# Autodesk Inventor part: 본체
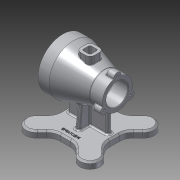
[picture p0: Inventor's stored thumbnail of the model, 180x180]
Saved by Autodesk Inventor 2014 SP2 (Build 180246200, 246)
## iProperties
Created: 2018-03
Part Number: 본체
Material: 알루미늄 6061
Document SubType Name: Modeling
Designer: 거성
Density: 2.71 g/cm^3
Appearance: 알루미늄 - 평지
Mass: 1030.73 g
Surface Area: 859.626 cm^2
Volume: 380.342 cm^3
Author: 거성
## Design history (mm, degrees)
sketch "스케치1"
  geometry: L1 (-50, 0)-(50, 0); L2 (-50, 36)-(-50, 45); L3 (-50, 45)-(-30, 45); L4 (-30, 45)-(27, 27.5); L5 (50, 27.5)-(50, 21); L6 (49, 20)-(23, 20); L7 (20, 23)-(20, 23); L8 (17, 26)-(-24, 26); L9 (-27, 29)-(-27, 32); L10 (-30, 35)-(-49, 35); L11 (27, 27.5)-(50, 27.5); L12 (-50, 36)-(-49, 35); L13 (49, 20)-(50, 21); A1 r 3 centre (-30, 32) between (-27, 32) and (-30, 35); A2 r 3 centre (-24, 29) between (-27, 29) and (-24, 26); A3 r 3 centre (17, 23) between (20, 23) and (17, 26); A4 r 3 centre (23, 23) between (20, 23) and (23, 20); 7 further points
  constraints: 26 end point, 10 point on line, 8 point on circle, 8 tangent, 7 parallel, 4 centre point, 3 equal radius, 2 perpendicular, 1 coincident, 1 horizontal, 1 midpoint
  dimensions: "d0" = 100 distance of L1.start L1.end; "d1" = 90 diameter of L3 L1; "d2" = 70 diameter of L10 L1; "d4" = 40 diameter of L6 L1; "d5" = 52 diameter of L8 L1; "d6" = 20 distance of L2.end L3.end; "d7" = 77 distance from line of L2 L4.end; "d8" = 100 distance between parallel lines of L5 L2; "d9" = 23 distance of point (-27, 35) point (-50, 35); "d10" = 47 distance of point (20, 26) point (-27, 26); "d11" = 55 diameter of L11 L1; "d12" = 49.99998 distance from line of L5 point (0, 0); "d13" = 3 radius of A1; "d14" = 1 distance of L2.start point (-50, 35); "d15" = 45 deg angle of L2 L12; "d16" = 1 distance of L6.start point (50, 20) (= d14); "d17" = 45 deg angle of L6 L13 (= d15)
revolve "회전1" sketch "스케치1" stored, may be unused: angle "d18" = 90 deg
node "작업 평면1"
sketch "스케치2"
  geometry: L1 (9.189, 45)-(-9.189, 45); L2 (-45, 9.189)-(-45, -9.189); L3 (44.289, 44.289)-(-44.289, -44.289); L4 (-45.7, 45.7)-(45.7, -45.7); L5 (115.887, 0)-(-115.887, 0); L6 (0, 0)-(84.957, -84.957); L7 (60.561, -35.105)-(52.322, -26.866); L8 (35.105, -60.561)-(26.866, -52.322); L9 (45, -9.189)-(45, 9.189); L10 (-9.189, -45)-(9.189, -45); L11 (35.105, 60.561)-(26.866, 52.322); L12 (60.561, 35.105)-(52.322, 26.866); L13 (0, 115.887)-(0, -115.887); L14 (-60.561, 35.105)-(-52.322, 26.866); L15 (-35.105, 60.561)-(-26.866, 52.322); L16 (-115.887, 0)-(115.887, 0); L17 (-35.105, -60.561)-(-26.866, -52.322); L18 (-60.561, -35.105)-(-52.322, -26.866); L19 (0, -115.887)-(0, 115.887); A1 r 70 centre (0, 0) between (49.497, -49.497) and (60.561, -35.105); A2 r 18.153 centre (49.497, -49.497) between (35.105, -60.561) and (60.561, -35.105); A3 r 18.153 centre (49.497, 49.497) between (60.561, 35.105) and (35.105, 60.561); A4 r 18.153 centre (-49.497, 49.497) between (-35.105, 60.561) and (-60.561, 35.105); A5 r 18.153 centre (-49.497, -49.497) between (-60.561, -35.105) and (-35.105, -60.561); A6 r 25 centre (70, -9.189) between (45, -9.189) and (52.322, -26.866); A7 r 25 centre (-70, 9.189) between (-45, 9.189) and (-52.322, 26.866); A8 r 25 centre (-70, -9.189) between (-52.322, -26.866) and (-45, -9.189); A9 r 25 centre (-9.189, -70) between (-9.189, -45) and (-26.866, -52.322); A10 r 25 centre (-9.189, 70) between (-26.866, 52.322) and (-9.189, 45); A11 r 25 centre (9.189, -70) between (26.866, -52.322) and (9.189, -45); A12 r 25 centre (70, 9.189) between (52.322, 26.866) and (45, 9.189); A13 r 25 centre (9.189, 70) between (9.189, 45) and (26.866, 52.322); 21 further points
  constraints: 38 end point, 27 point on circle, 17 point on line, 16 tangent, 13 centre point, 11 midpoint, 7 coincident, 5 parallel, 3 equal radius, 2 perpendicular, 1 collinear, 1 horizontal, 51 other
  dimensions: "d20" = 90 distance of L4.end L3.end; "d21" = 90 distance of L3.end L4.start; "d22" = 140 diameter of A1; "d23" = 45 deg angle of L6 L5 (derived); "d27" = 360 deg dimension on point (0, 0) L7.start (derived); "d29" = 90 distance between parallel lines of L2 L9; "d30" = 36 distance between parallel lines of L11 L12; "d33" = 25 radius of A6; "d34" = 25 radius of A7; "d35" = 90 distance between parallel lines of L10 L1 (derived); "d36" = 25 radius of A10; "d37" = 25 radius of A11; "d38" = 25 radius of A12
extrude "돌출1" join sketch "스케치2" distance "d39" = 12; taper "d40" = 0 deg
sketch "스케치3" dims "d62" = 7
  geometry: L1 (9.189, 45)-(-9.189, 45) reference; L2 (-37, 0)-(37, 0); L3 (-37, 0)-(-33, 0); L4 (37, 0)-(33, 0); L5 (-33, 0)-(33, 0); L6 (-33, -4)-(33, -4); L7 (33, 4)-(-33, 4); A1 r 4 centre (-33, 0) between (-33, 4) and (-33, -4); A2 r 4 centre (33, 0) between (33, -4) and (33, 4); 3 further points
  constraints: 14 end point, 4 point on circle, 4 tangent, 2 centre point, 2 midpoint, 2 parallel, 2 point on line, 1 coincident, 1 collinear
  dimensions: "d41" = 74 distance of L2.start L2.end; "d42" = 4 distance of L2.start L3.end; "d43" = 4 distance of L2.end L4.end; "d44" = 8 distance between parallel lines of L6 L7
extrude "돌출2" join sketch "스케치3" stored distance "d45" = 12; taper "d46" = 0 deg
sketch "스케치4"
  geometry: L1 (-33, 4)-(33, 4) reference; L2 (33, -4)-(-33, -4) reference; L3 (-60.561, 35.105)-(-52.322, 26.866) reference; L4 (-45, 9.189)-(-45, -9.189) reference; L5 (-52.322, -26.866)-(-60.561, -35.105) reference; L6 (-35.105, -60.561)-(-26.866, -52.322) reference; L7 (-9.189, -45)-(9.189, -45) reference; L8 (26.866, -52.322)-(35.105, -60.561) reference; L9 (60.561, -35.105)-(52.322, -26.866) reference; L10 (45, -9.189)-(45, 9.189) reference; L11 (52.322, 26.866)-(60.561, 35.105) reference; L12 (35.105, 60.561)-(26.866, 52.322) reference; L13 (9.189, 45)-(-9.189, 45) reference; L14 (-26.866, 52.322)-(-35.105, 60.561) reference; L15 (0, -24)-(0, 24); L16 (0, -24)-(0, -20); L17 (0, 24)-(0, 20); L18 (0, -20)-(0, 20); L19 (4, -20)-(4, 20); L20 (-4, 20)-(-4, -20); A1 r 4 centre (-33, 0) between (-33, 4) and (-33, -4) reference; A2 r 4 centre (33, 0) between (33, -4) and (33, 4) reference; A3 r 25 centre (-70, 9.189) between (-45, 9.189) and (-52.322, 26.866) reference; A4 r 25 centre (-70, -9.189) between (-52.322, -26.866) and (-45, -9.189) reference; A5 r 18.153 centre (-49.497, -49.497) between (-60.561, -35.105) and (-35.105, -60.561) reference; A6 r 25 centre (-9.189, -70) between (-9.189, -45) and (-26.866, -52.322) reference; A7 r 25 centre (9.189, -70) between (26.866, -52.322) and (9.189, -45) reference; A8 r 18.153 centre (49.497, -49.497) between (35.105, -60.561) and (60.561, -35.105) reference; A9 r 25 centre (70, -9.189) between (45, -9.189) and (52.322, -26.866) reference; A10 r 25 centre (70, 9.189) between (52.322, 26.866) and (45, 9.189) reference; A11 r 18.153 centre (49.497, 49.497) between (60.561, 35.105) and (35.105, 60.561) reference; A12 r 25 centre (9.189, 70) between (9.189, 45) and (26.866, 52.322) reference; A13 r 25 centre (-9.189, 70) between (-26.866, 52.322) and (-9.189, 45) reference; A14 r 18.153 centre (-49.497, 49.497) between (-35.105, 60.561) and (-60.561, 35.105) reference; A15 r 4 centre (0, -20) between (-4, -20) and (4, -20); A16 r 4 centre (0, 20) between (4, 20) and (-4, 20); 3 further points
  constraints: 14 end point, 4 point on circle, 4 tangent, 2 centre point, 2 midpoint, 2 parallel, 2 point on line, 1 coincident, 1 perpendicular
  dimensions: "d47" = 48 distance of L15.start L15.end; "d48" = 4 distance of L15.start L16.end; "d49" = 4 distance of L15.end L17.end; "d50" = 8 diameter of A16
node "작업 평면2"
sketch "스케치5"
  geometry: L1 (-70.227, 0)-(-70.227, -24); L2 (-70.227, -24)-(-17.34, -19.373); L3 (-70, -35.105)-(-70, -26.866) reference; 2 further points
  constraints: 4 end point, 1 vertical, 2 other
  dimensions: "d52" = 24 distance of L1.start L1.end; "d53" = 95 deg angle of L3 L2
feature "리브1" sketch "스케치5" dims "d54" = 1, "d55" = 8, "d56" = 0, "d57" = 0, "d58" = 1, "d59" = 1
node "작업 평면3"
sketch "스케치6"
  geometry: L1 (0, 0)-(0, 27.5); C1 r 21 at (0, 0) reference; A1 r 27.5 centre (0, 0) between (6.943, 26.609) and (-6.943, 26.609); A2 r 7 centre (0, 27.5) between (6.943, 26.609) and (-6.943, 26.609); 1 further point
  constraints: 4 point on circle, 2 centre point, 2 coincident, 2 end point, 1 vertical, 1 vertical alignment, 2 other
  dimensions: "d62" = 7 radius of A2
extrude "돌출3" join sketch "스케치6" distance "d63" = 15; taper "d64" = 0 deg
node "작업 평면5"
sketch "스케치7"
  geometry: L1 (12.5, 12.5)-(-12.5, 12.5); L2 (-12.5, 12.5)-(-12.5, -12.5); L3 (-12.5, -12.5)-(12.5, -12.5); L4 (12.5, -12.5)-(12.5, 12.5); L5 (12.5, 12.5)-(-12.5, -12.5); L6 (-12.5, 12.5)-(12.5, -12.5); 1 further point
  constraints: 12 end point, 2 midpoint, 2 parallel, 1 horizontal, 1 perpendicular
  dimensions: "d66" = 25 distance of L3.end L2.end; "d67" = 25 distance of L2.end L1.end
extrude "돌출4" join sketch "스케치7" stored distance "d68" = 15; taper "d69" = 0 deg
sketch "스케치8"
  geometry: L1 (-4.5, 7.5)-(4.5, 7.5); L2 (7.5, 4.5)-(7.5, -4.5); L3 (4.5, -7.5)-(-4.5, -7.5); L4 (-7.5, -4.5)-(-7.5, 4.5); L5 (-7.5, 7.5)-(7.5, -7.5); L6 (7.5, 7.5)-(-7.5, -7.5); A1 r 3 centre (4.5, 4.5) between (7.5, 4.5) and (4.5, 7.5); A2 r 3 centre (-4.5, 4.5) between (-4.5, 7.5) and (-7.5, 4.5); A3 r 3 centre (-4.5, -4.5) between (-7.5, -4.5) and (-4.5, -7.5); A4 r 3 centre (4.5, -4.5) between (4.5, -7.5) and (7.5, -4.5); 1 further point
  constraints: 12 end point, 8 point on circle, 8 point on line, 8 tangent, 4 centre point, 3 equal radius, 2 midpoint, 2 parallel, 1 horizontal, 1 perpendicular
  dimensions: "d70" = 15 distance of L5.end L6.end; "d71" = 15 distance of L6.start L5.end; "d72" = 3 radius of A1
extrude "돌출5" cut sketch "스케치8" stored distance "d73" = 15; taper "d74" = 0 deg
fillet "모깎기1" dims "d75" = 8
fillet "모깎기2" dims "d76" = 1
fillet "모깎기3" dims "d77" = 3
fillet "모깎기4" dims "d78" = 1
sketch "스케치9" dims "d79" = 80
  geometry: L1 (0, 0)-(0, 40); C1 r 45 at (0, 0) reference; 1 further point
  constraints: 2 coincident, 2 end point, 1 vertical, 1 vertical alignment, 2 other
hole "구멍1" sketch "스케치9" at (0, 40) diameter "d80" = 4.917; stored, may be unused: countersink angle "d84" = 90 deg, drill point angle "d86" = 118 deg; dims "d81" = 9, "d82" = 4, "d83" = 2, "d85" = 11
sketch "스케치10"
  geometry: C1 r 21 at (0, -27.5) reference; A1 r 27.5 centre (0, -27.5) between (-7.718, -1.105) and (7.718, -1.105) reference; A2 r 1 centre (7.999, -0.145) between (6.999, -0.127) and (7.718, -1.105) reference; A3 r 7 centre (0, 0) between (6.999, -0.127) and (-6.999, -0.127) reference; A4 r 1 centre (-7.999, -0.145) between (-7.718, -1.105) and (-6.999, -0.127) reference
hole "구멍2" diameter "d92" = 3.242; stored, may be unused: countersink angle "d96" = 90 deg, drill point angle "d98" = 118 deg; dims "d90" = 10, "d91" = 10, "d93" = 9, "d94" = 4, "d95" = 2, "d97" = 11
sketch "스케치11"
  geometry: 2 further points
  constraints: 1 vertical alignment, 1 other
  dimensions: "d102" = 35 distance of point (0, 0) point (0, -35)
feature "엠보싱1" sketch "스케치11" dims "d0" = 100, "d1" = 90, "d2" = 70, "d4" = 40, "d5" = 52, "d6" = 20, "d7" = 77, "d8" = 100, "d9" = 23, "d10" = 47, "d11" = 55, "d12" = 49.99998, "d13" = 3, "d14" = 1, "d15" = 45 deg, "d16" = 1 (= d14), "d17" = 45 deg (= d15), "d103" = 0.5, "d104" = 0
fillet "모깎기5" dims "d105" = 3
fillet "모깎기6" dims "d106" = 3
fillet "모깎기7" dims "d107" = 3
fillet "모깎기8" dims "d108" = 3
fillet "모깎기9" dims "d109" = 3
chamfer "모따기1" distance "d110" = 3; stored, may be unused: second distance "d111" = 2, angle "d112" = 45 deg
chamfer "모따기2" distance "d113" = 3; stored, may be unused: second distance "d114" = 2, angle "d115" = 45 deg
chamfer "모따기3" distance "d116" = 3; stored, may be unused: second distance "d117" = 2, angle "d118" = 45 deg
node "솔리드1"
mirror "대칭1"
pattern_circular "원형 패턴1" dims angle "d88" = 360 deg
pattern_circular "원형 패턴2" dims "d100" = 360 deg
node "작업 평면4"
other parameters: "d19" = -82, "d24" = 36, "d51" = 0, "d60" = 0, "d61" = 14, "d65" = 45
